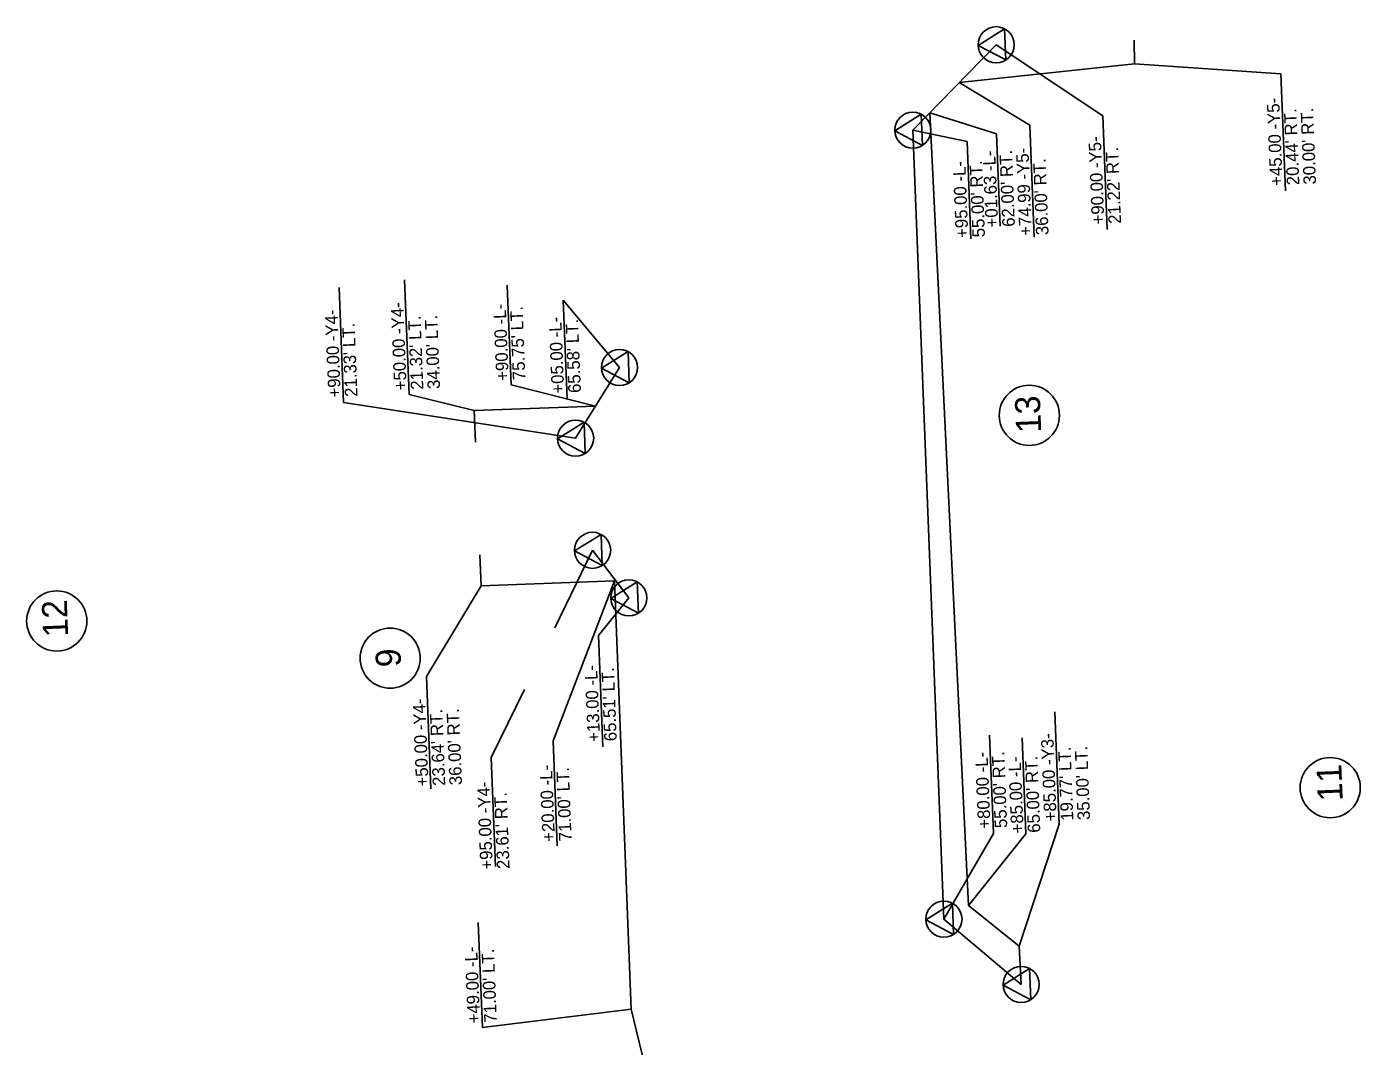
# Model space of a CAD drawing. Extents: x 1627970 to 1628801, y 761752 to 765698.
# Drawn here: x 1628158 to 1628689, y 762507 to 762913 of the extents above; entities that cross this region are included whole.
import ezdxf

# ---------------------------------------------------------------- set-up
doc = ezdxf.new("R2010")
doc.units = 0
for name, color, linetype in [('Exist Property Line Text', 7, 'Continuous'), ('Exist Right of Way Control of Access Line', 7, 'Continuous'), ('Exist Right of Way Monument Text', 7, 'Continuous'), ('Exist Utilities Gas UG Line', 7, 'Continuous'), ('Exist Utilities Gas UG Line Text', 7, 'Continuous'), ('Exist Utilities Other Unknown UG SUE Text', 7, 'Continuous')]:
    doc.layers.add(name, color=color, linetype=linetype)

msp = doc.modelspace()

# ---------------------------------------------------------------- linework, layer by layer
at = {"layer": 'Exist Property Line Text'}
for p, q in [((1628557.37, 762758.25), (1628557.37, 762758.25)), ((1628169.5, 762676.21), (1628169.5, 762676.21)), ((1628302.46, 762661.37), (1628302.46, 762661.37)), ((1628677.37, 762609.73), (1628677.37, 762609.73))]:
    msp.add_line(p, q, dxfattribs=at)
for centre in [(1628557.37, 762758.25), (1628169.5, 762676.21), (1628302.46, 762661.37), (1628677.37, 762609.73)]:
    msp.add_circle(centre, 12, dxfattribs=at)
at = {"layer": 'Exist Right of Way Control of Access Line'}
for p, q in [((1628510.91, 762872.01), (1628544.16, 762906.11)), ((1628523.32, 762557.26), (1628510.91, 762872.01)), ((1628376.43, 762749.12), (1628393.96, 762777.33)), ((1628383.21, 762704.41), (1628397.66, 762685.41)), ((1628554.13, 762531.23), (1628523.32, 762557.26))]:
    msp.add_line(p, q, dxfattribs=at)
at = {"layer": 'Exist Right of Way Monument Text'}
for p, q in [((1628599.32, 762898.42), (1628599.13, 762907.98)), ((1628529.45, 762891.03), (1628599.32, 762898.42)), ((1628533.11, 762562.65), (1628517.64, 762878.92)), ((1628335.96, 762760.19), (1628384.4, 762761.94)), ((1628336.46, 762747.52), (1628335.96, 762760.19)), ((1628338.73, 762690.25), (1628338.24, 762702.6)), ((1628391.9, 762692.18), (1628338.73, 762690.25)), ((1628398.64, 762521.32), (1628391.9, 762692.18)), ((1628553.36, 762546.44), (1628533.11, 762562.65)), ((1628554.13, 762531.23), (1628553.36, 762546.44)), ((1628405.16, 762494.55), (1628398.64, 762521.32))]:
    msp.add_line(p, q, dxfattribs=at)
at = {"layer": 'Exist Utilities Gas UG Line'}
for p, q in [((1628586.63, 762877.71), (1628544.16, 762906.11)), ((1628586.63, 762877.71), (1628588.42, 762832.44)), ((1628510.91, 762872.01), (1628532.56, 762867.51)), ((1628532.56, 762867.51), (1628534.08, 762828.73)), ((1628282.09, 762809.22), (1628283.9, 762763.4)), ((1628371.46, 762804.22), (1628373.01, 762764.94)), ((1628393.96, 762777.33), (1628371.46, 762804.22)), ((1628376.43, 762749.12), (1628283.9, 762763.4)), ((1628368.08, 762673.53), (1628383.21, 762704.41)), ((1628385.56, 762670.38), (1628397.66, 762685.41)), ((1628385.56, 762670.38), (1628387.31, 762626.02)), ((1628342.71, 762621.75), (1628356.01, 762648.88)), ((1628567.5, 762640.03), (1628569.27, 762595.16)), ((1628541.47, 762630.66), (1628543.02, 762591.38)), ((1628342.71, 762621.75), (1628344.43, 762578.22)), ((1628523.32, 762557.26), (1628543.02, 762591.38)), ((1628553.36, 762546.44), (1628569.27, 762595.16))]:
    msp.add_line(p, q, dxfattribs=at)
at = {"layer": 'Exist Utilities Gas UG Line Text'}
for p, q in [((1628657.69, 762894.46), (1628599.32, 762898.42)), ((1628657.69, 762894.46), (1628659.53, 762847.83)), ((1628557.51, 762874.02), (1628529.45, 762891.03)), ((1628544.33, 762870.6), (1628517.64, 762878.92)), ((1628557.51, 762874.02), (1628559.27, 762829.36)), ((1628544.33, 762870.6), (1628545.78, 762833.76)), ((1628308.18, 762812.25), (1628309.98, 762766.58)), ((1628349.11, 762810.15), (1628350.68, 762770.38)), ((1628309.98, 762766.58), (1628335.96, 762760.19)), ((1628350.68, 762770.38), (1628384.4, 762761.94)), ((1628367.46, 762628.42), (1628391.9, 762692.18)), ((1628316.91, 762654), (1628338.73, 762690.25)), ((1628316.91, 762654), (1628318.68, 762609.28)), ((1628367.46, 762628.42), (1628369.12, 762586.45)), ((1628554.46, 762629.59), (1628555.97, 762591.35)), ((1628533.11, 762562.65), (1628555.97, 762591.35)), ((1628337.62, 762555.99), (1628339.28, 762514.02)), ((1628339.28, 762514.02), (1628398.64, 762521.32))]:
    msp.add_line(p, q, dxfattribs=at)
at = {"layer": 'Exist Utilities Other Unknown UG SUE Text'}
for p, q in [((1628544.16, 762906.11), (1628544.16, 762906.11)), ((1628510.91, 762872.01), (1628510.91, 762872.01)), ((1628393.96, 762777.33), (1628393.96, 762777.33)), ((1628376.43, 762749.12), (1628376.43, 762749.12)), ((1628383.21, 762704.41), (1628383.21, 762704.41)), ((1628397.66, 762685.41), (1628397.66, 762685.41)), ((1628523.32, 762557.26), (1628523.32, 762557.26)), ((1628554.13, 762531.23), (1628554.13, 762531.23))]:
    msp.add_line(p, q, dxfattribs=at)
for points in [[(1628536.95, 762905.84), (1628547.52, 762912.48), (1628548.01, 762900.01)], [(1628503.7, 762871.74), (1628514.26, 762878.38), (1628514.76, 762865.91)], [(1628386.76, 762777.06), (1628397.32, 762783.7), (1628397.81, 762771.23)], [(1628369.22, 762748.85), (1628379.79, 762755.49), (1628380.28, 762743.02)], [(1628376, 762704.14), (1628386.57, 762710.78), (1628387.06, 762698.31)], [(1628390.45, 762685.14), (1628401.01, 762691.78), (1628401.51, 762679.31)], [(1628516.11, 762556.99), (1628526.68, 762563.63), (1628527.17, 762551.16)], [(1628546.93, 762530.96), (1628557.49, 762537.6), (1628557.98, 762525.13)]]:
    msp.add_lwpolyline(points, close=True, dxfattribs=at)
for centre in [(1628544.16, 762906.11), (1628510.91, 762872.01), (1628393.96, 762777.33), (1628376.43, 762749.12), (1628383.21, 762704.41), (1628397.66, 762685.41), (1628523.32, 762557.26), (1628554.13, 762531.23)]:
    msp.add_circle(centre, 7.2, dxfattribs=at)

# ---------------------------------------------------------------- texts
at = {"layer": 'Exist Property Line Text'}
for s, p in [('13', (1628562.13, 762751.44)), ('12', (1628174.08, 762669.97)), ('9', (1628306.84, 762657.99)), ('11', (1628682.37, 762604.45))]:
    msp.add_text(s, height=10, rotation=92.2582, dxfattribs=at).set_placement(p)
at = {"layer": 'Exist Utilities Gas UG Line'}
for s, p in [('+90.00 -Y5-', (1628587.31, 762834.51)), ("21.22' RT.", (1628593.97, 762834.77)), ('+95.00 -L-', (1628533.04, 762829.11)), ("55.00' RT.", (1628539.7, 762829.38)), ('+90.00 -Y4-', (1628282.79, 762765.46)), ("21.33' LT.", (1628289.45, 762765.72)), ('+05.00 -L-', (1628371.9, 762767)), ("65.58' LT.", (1628378.56, 762767.27)), ('+13.00 -L-', (1628386.2, 762628.08)), ("65.51' LT.", (1628392.86, 762628.34)), ('+85.00 -Y3-', (1628568.3, 762596.37)), ('+80.00 -L-', (1628541.91, 762593.44)), ("55.00' RT.", (1628548.57, 762593.7)), ("19.77' LT.", (1628574.96, 762596.63)), ("35.00' LT.", (1628581.62, 762596.89)), ('+95.00 -Y4-', (1628343.45, 762577.12)), ("23.61' RT.", (1628350.11, 762577.39))]:
    msp.add_text(s, height=5, rotation=92.2582, dxfattribs=at).set_placement(p)
at = {"layer": 'Exist Utilities Gas UG Line Text'}
for s, p in [('+45.00 -Y5-', (1628658.42, 762849.89)), ("20.44' RT.", (1628665.08, 762850.15)), ("30.00' RT.", (1628671.74, 762850.42)), ('+01.63 -L-', (1628544.96, 762833.3)), ("62.00' RT.", (1628551.62, 762833.56)), ('+74.99 -Y5-', (1628558.4, 762829.96)), ("36.00' RT.", (1628565.06, 762830.22)), ('+50.00 -Y4-', (1628309.07, 762768.33)), ("21.32' LT.", (1628315.73, 762768.6)), ("34.00' LT.", (1628322.39, 762768.86)), ('+90.00 -L-', (1628349.77, 762772.13)), ("75.75' LT.", (1628356.43, 762772.39)), ('+50.00 -Y4-', (1628317.8, 762610.28)), ("23.64' RT.", (1628324.46, 762610.54)), ("36.00' RT.", (1628331.12, 762610.81)), ('+85.00 -L-', (1628555.12, 762591.56)), ("65.00' RT.", (1628561.78, 762591.82)), ('+20.00 -L-', (1628368.21, 762588.21)), ("71.00' LT.", (1628374.87, 762588.47)), ('+49.00 -L-', (1628338.37, 762515.77)), ("71.00' LT.", (1628345.03, 762516.04))]:
    msp.add_text(s, height=5, rotation=92.2582, dxfattribs=at).set_placement(p)

doc.saveas('drawing.dxf')
